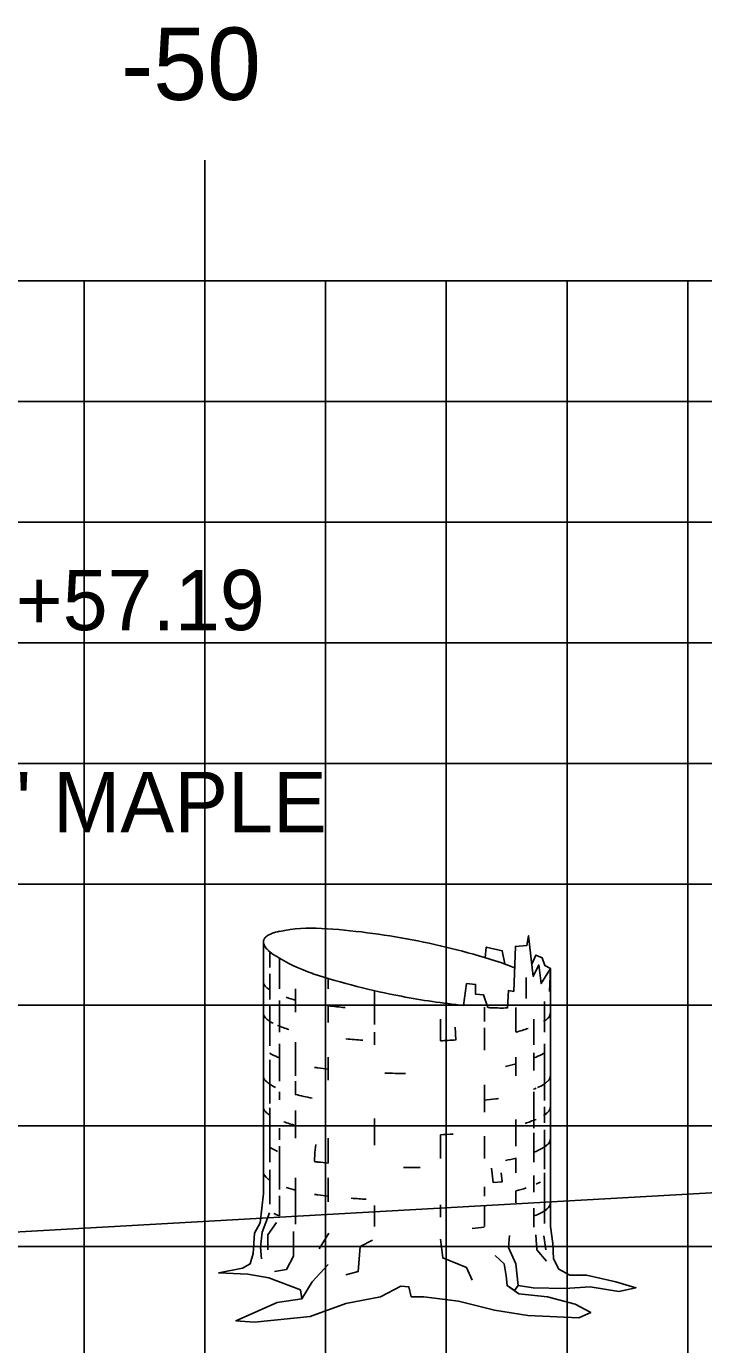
# Model space of a CAD drawing. Extents: x 854676 to 854846, y 366268 to 366378.
# Drawn here: x 854707.63 to 854713.24, y 366308.42 to 366319.35 of the extents above; entities that cross this region are included whole.
import ezdxf

# ---------------------------------------------------------------- set-up
doc = ezdxf.new("R2010")
doc.units = 0
for name, color, linetype in [('D_Text_Monospaced', 7, 'Continuous'), ('H_V ANNOTATION', 7, 'Continuous'), ('MAJOR', 7, 'Continuous'), ('MINOR', 7, 'Continuous'), ('S_Roadway_Centerline', 7, 'Continuous'), ('S_Trees_Decid_Pay', 7, 'Continuous')]:
    doc.layers.add(name, color=color, linetype=linetype)

msp = doc.modelspace()

# ---------------------------------------------------------------- linework, layer by layer
at = {"layer": 'MAJOR'}
for p, q in [((854709.106, 366318.238), (854709.106, 366317.236)), ((854689.106, 366317.236), (854829.106, 366317.236)), ((854689.106, 366317.236), (854829.106, 366317.236)), ((854709.106, 366302.236), (854709.106, 366317.236)), ((854689.106, 366312.236), (854829.106, 366312.236))]:
    msp.add_line(p, q, dxfattribs=at)
at = {"layer": 'MINOR'}
for p, q in [((854708.106, 366302.236), (854708.106, 366317.236)), ((854710.106, 366302.236), (854710.106, 366317.236)), ((854711.106, 366302.236), (854711.106, 366317.236)), ((854712.106, 366302.236), (854712.106, 366317.236)), ((854713.106, 366302.236), (854713.106, 366317.236)), ((854689.106, 366316.236), (854829.106, 366316.236)), ((854689.106, 366315.236), (854829.106, 366315.236)), ((854689.106, 366314.236), (854829.106, 366314.236)), ((854689.106, 366313.236), (854829.106, 366313.236)), ((854689.106, 366311.236), (854829.106, 366311.236)), ((854689.106, 366310.236), (854829.106, 366310.236)), ((854689.106, 366309.236), (854829.106, 366309.236))]:
    msp.add_line(p, q, dxfattribs=at)
at = {"layer": 'S_Roadway_Centerline'}
msp.add_lwpolyline([(854702.478, 366309.069), (854721.133, 366310.121), (854725.449, 366310.212), (854732.94, 366310.746), (854735.545, 366310.37), (854737.315, 366310.547), (854738.261, 366310.513), (854740.788, 366310.363), (854741.663, 366310.048), (854741.948, 366309.957), (854743.884, 366310.025), (854748.429, 366310.204), (854751.474, 366310.169), (854759.551, 366310.169), (854768.432, 366309.965), (854771.526, 366309.892)], dxfattribs=at)
at = {"layer": 'S_Trees_Decid_Pay'}
for p, q in [((854709.643, 366311.668), (854709.643, 366311.547)), ((854709.723, 366311.623), (854709.723, 366311.37)), ((854709.643, 366311.495), (854709.643, 366311.281)), ((854710.128, 366311.457), (854710.128, 366311.37)), ((854711.768, 366311.465), (854711.768, 366311.29)), ((854709.856, 366311.37), (854709.856, 366311.178)), ((854710.511, 366311.356), (854710.511, 366311.075)), ((854709.643, 366311.236), (854709.643, 366310.898)), ((854709.723, 366311.274), (854709.723, 366311.01)), ((854710.128, 366311.229), (854710.128, 366311.09)), ((854711.422, 366311.218), (854711.422, 366311.098)), ((854711.683, 366311.216), (854711.683, 366311.011)), ((854711.918, 366311.264), (854711.918, 366311.01)), ((854711.057, 366311.119), (854711.057, 366310.939)), ((854711.832, 366311.119), (854711.832, 366310.907)), ((854710.511, 366311.01), (854710.511, 366310.907)), ((854711.184, 366310.946), (854711.179, 366311.053)), ((854711.422, 366311.047), (854711.422, 366310.862)), ((854709.723, 366310.913), (854709.723, 366310.604)), ((854709.856, 366310.927), (854709.856, 366310.65)), ((854711.832, 366310.841), (854711.832, 366310.693)), ((854711.918, 366310.913), (854711.918, 366310.444)), ((854709.643, 366310.781), (854709.643, 366310.421)), ((854710.128, 366310.804), (854710.128, 366310.612)), ((854711.683, 366310.804), (854711.683, 366310.65)), ((854709.723, 366310.516), (854709.723, 366310.449)), ((854709.856, 366310.604), (854709.856, 366310.495)), ((854711.422, 366310.575), (854711.422, 366310.347)), ((854711.832, 366310.516), (854711.832, 366310.215)), ((854709.643, 366310.384), (854709.643, 366309.935)), ((854709.856, 366310.361), (854709.856, 366310.133)), ((854710.511, 366310.295), (854710.511, 366310.075)), ((854711.918, 366310.392), (854711.918, 366310.259)), ((854709.723, 366310.215), (854709.723, 366310.118)), ((854711.683, 366310.287), (854711.683, 366310.067)), ((854711.918, 366310.201), (854711.918, 366309.875)), ((854710.128, 366310.133), (854710.128, 366309.925)), ((854711.057, 366310.161), (854711.057, 366309.964)), ((854711.422, 366310.149), (854711.422, 366309.964)), ((854711.832, 366310.178), (854711.832, 366309.935)), ((854709.723, 366310.067), (854709.723, 366309.707)), ((854711.683, 366309.967), (854711.683, 366309.846)), ((854709.643, 366309.869), (854709.643, 366309.587)), ((854709.856, 366309.803), (854709.856, 366309.42)), ((854710.128, 366309.803), (854710.128, 366309.604)), ((854711.832, 366309.824), (854711.832, 366309.684)), ((854711.918, 366309.846), (854711.918, 366309.426)), ((854709.723, 366309.655), (854709.723, 366309.488)), ((854711.422, 366309.729), (854711.422, 366309.652)), ((854711.683, 366309.696), (854711.683, 366309.597)), ((854710.511, 366309.575), (854710.511, 366309.402)), ((854711.057, 366309.581), (854711.057, 366309.478)), ((854711.422, 366309.575), (854711.422, 366309.402)), ((854711.832, 366309.552), (854711.832, 366309.396)), ((854710.133, 366309.346), (854710.053, 366309.215)), ((854711.914, 366309.323), (854711.929, 366309.206))]:
    msp.add_line(p, q, dxfattribs=at)
for points in [[(854711.968, 366311.539), (854711.968, 366309.402), (854711.989, 366309.26), (854711.994, 366309.134), (854712.038, 366309.047), (854712.13, 366308.998), (854712.266, 366308.998), (854712.509, 366308.942), (854712.676, 366308.893), (854712.534, 366308.862), (854712.297, 366308.9), (854712.087, 366308.887), (854711.826, 366308.893), (854711.702, 366308.911), (854711.672, 366308.869), (854711.609, 366308.911), (854711.708, 366308.844), (854711.943, 366308.819), (854712.174, 366308.757), (854712.303, 366308.687), (854712.204, 366308.644), (854711.782, 366308.663), (854711.504, 366308.706), (854711.206, 366308.782), (854710.92, 366308.819), (854710.815, 366308.819), (854710.796, 366308.9), (854710.728, 366308.905), (854710.561, 366308.819), (854710.275, 366308.763), (854709.977, 366308.656), (854709.517, 366308.607), (854709.363, 366308.619), (854709.705, 366308.77), (854709.908, 366308.801), (854709.897, 366308.875), (854709.637, 366308.974), (854709.462, 366309.005), (854709.221, 366309.016), (854709.419, 366309.054), (854709.481, 366309.091), (854709.505, 366309.177), (854709.517, 366309.346), (854709.563, 366309.432), (854709.591, 366309.673), (854709.591, 366311.759)], [(854711.59, 366311.577), (854711.569, 366311.685), (854711.437, 366311.716), (854711.429, 366311.628)], [(854711.612, 366311.211), (854711.62, 366311.356), (854711.665, 366311.348), (854711.679, 366311.722), (854711.774, 366311.73), (854711.788, 366311.81), (854711.826, 366311.473), (854711.871, 366311.568), (854711.891, 366311.413), (854711.968, 366311.539), (854711.962, 366311.349)], [(854711.968, 366311.539), (854711.922, 366311.562), (854711.9, 366311.627), (854711.848, 366311.65), (854711.815, 366311.575)], [(854711.45, 366311.216), (854711.414, 366311.319), (854711.348, 366311.325), (854711.348, 366311.407), (854711.274, 366311.413), (854711.249, 366311.233)], [(854710.015, 366309.938), (854710.016, 366310.015), (854710.024, 366310.081)], [(854711.56, 366309.846), (854711.569, 366309.772), (854711.494, 366309.766), (854711.48, 366309.883)], [(854709.641, 366309.515), (854709.581, 366309.354), (854709.567, 366309.229), (854709.575, 366309.132)], [(854709.698, 366309.434), (854709.627, 366309.331), (854709.627, 366309.206)], [(854709.839, 366309.36), (854709.839, 366309.155), (854709.781, 366309.045), (854709.684, 366309.029)], [(854711.702, 366308.911), (854711.683, 366309.091), (854711.622, 366309.227), (854711.628, 366309.327)], [(854711.848, 366309.331), (854711.855, 366309.206), (854711.937, 366309.112)], [(854710.494, 366309.286), (854710.391, 366309.235), (854710.376, 366309.029), (854710.273, 366309)], [(854711.059, 366309.295), (854711.076, 366309.14), (854711.274, 366309.06), (854711.319, 366308.957)], [(854711.511, 366309.159), (854711.585, 366309.091), (854711.603, 366308.992), (854711.609, 366308.911)], [(854709.908, 366308.801), (854709.995, 366308.942), (854710.127, 366309.085)]]:
    msp.add_lwpolyline(points, dxfattribs=at)
for centre, radius, start, end in [((854709.715, 366311.673), 0.164, 110.0157, 124.2221), ((854709.823, 366311.377), 0.48, 101.7221, 110.0157), ((854709.989, 366310.574), 1.299, 86.3056, 101.7221), ((854709.678, 366305.758), 6.126, 79.2221, 86.3056), ((854709.637, 366311.759), 0.0467, 169.2221, 180.9043), ((854709.645, 366311.759), 0.0544, 180.9043, 191.7221), ((854709.637, 366311.759), 0.0467, 157.54, 169.2221), ((854709.655, 366311.762), 0.0645, 191.7221, 204.3989), ((854709.645, 366311.756), 0.0544, 146.7221, 157.54), ((854709.694, 366311.779), 0.107, 204.3989, 214.2221), ((854709.653, 366311.751), 0.0645, 134.0453, 146.7221), ((854709.741, 366311.811), 0.164, 214.2221, 228.4286), ((854709.683, 366311.72), 0.107, 124.2221, 134.0453), ((854709.678, 366305.758), 6.126, 72.1387, 79.2221), ((854709.95, 366312.047), 0.48, 228.4286, 236.7221), ((854710.4, 366312.733), 1.299, 236.7221, 252.1387), ((854711.88, 366317.326), 6.126, 252.1387, 259.2221), ((854711.158, 366310.351), 1.299, 66.6931, 72.1387), ((854709.645, 366311.433), 0.0554, 191.6815, 202.5), ((854709.654, 366311.437), 0.0657, 202.5, 215.1737), ((854709.69, 366311.462), 0.109, 215.1737, 225), ((854709.731, 366311.502), 0.166, 225, 238.33), ((854710.202, 366312.521), 1.292, 250.9084, 254.4349), ((854711.88, 366317.326), 6.126, 259.2221, 264.0853), ((854710.778, 366317.109), 5.916, 263.6913, 265.0485), ((854711.88, 366317.326), 6.126, 265.9754, 266.3056), ((854711.569, 366312.51), 1.299, 266.3056, 271.8711), ((854711.92, 366311.17), 0.0476, 348.3185, 0), ((854709.646, 366311.172), 0.0554, 191.6815, 202.5), ((854709.655, 366311.176), 0.0657, 202.5, 215.1737), ((854709.691, 366311.201), 0.109, 215.1737, 225), ((854709.732, 366311.241), 0.166, 225, 239.1924), ((854709.894, 366311.514), 0.484, 239.1924, 242.5838), ((854710.203, 366312.261), 1.292, 247.5, 251.9171), ((854711.827, 366311.241), 0.166, 300.8076, 315), ((854711.868, 366311.201), 0.109, 315, 324.8263), ((854711.903, 366311.176), 0.0657, 324.8263, 337.5), ((854711.913, 366311.172), 0.0554, 337.5, 348.3185), ((854710.779, 366316.849), 5.916, 265.1076, 266.4618), ((854711.355, 366312.261), 1.292, 284.7144, 289.3881), ((854710.779, 366316.849), 5.916, 272.6957, 273.9224), ((854711.827, 366310.978), 0.166, 300.8076, 302.9622), ((854709.732, 366310.978), 0.166, 238.3999, 239.1924), ((854709.894, 366311.251), 0.484, 239.1924, 247.5), ((854710.203, 366311.997), 1.292, 247.5, 248.1929), ((854711.355, 366311.997), 1.292, 280.7368, 284.7144), ((854711.355, 366311.997), 1.292, 291.6463, 292.5), ((854711.664, 366311.251), 0.484, 292.5, 300.8076), ((854709.646, 366310.651), 0.0554, 191.6815, 202.5), ((854709.655, 366310.655), 0.0657, 202.5, 215.1737), ((854710.203, 366311.997), 1.292, 261.6338, 262.8454), ((854710.779, 366316.585), 5.916, 262.8454, 263.6816), ((854710.779, 366316.585), 5.916, 268.2292, 269.8838), ((854711.903, 366310.655), 0.0657, 324.8263, 337.5), ((854711.913, 366310.651), 0.0554, 337.5, 348.3185), ((854711.92, 366310.649), 0.0476, 348.3185, 0), ((854709.691, 366310.68), 0.109, 215.1737, 225), ((854709.732, 366310.721), 0.166, 225, 239.1924), ((854709.894, 366310.993), 0.484, 239.1924, 245.3628), ((854711.355, 366311.74), 1.292, 291.5158, 292.5), ((854711.664, 366310.993), 0.484, 294.2275, 300.8076), ((854711.827, 366310.721), 0.166, 300.8076, 315), ((854711.868, 366310.68), 0.109, 315, 324.8263), ((854710.203, 366311.74), 1.292, 254.3895, 260.7435), ((854710.779, 366316.328), 5.916, 276.2405, 277.1546), ((854711.355, 366311.74), 1.292, 277.1546, 278.1274), ((854709.646, 366310.394), 0.0554, 191.6815, 202.5), ((854709.655, 366310.398), 0.0657, 202.5, 215.1737), ((854709.691, 366310.423), 0.109, 215.1737, 225), ((854709.732, 366310.463), 0.166, 225, 237.9306), ((854711.827, 366310.463), 0.166, 300.8076, 315), ((854711.868, 366310.423), 0.109, 315, 324.8263), ((854711.903, 366310.398), 0.0657, 324.8263, 337.5), ((854711.913, 366310.394), 0.0554, 337.5, 348.3185), ((854711.92, 366310.392), 0.0476, 348.3185, 0), ((854710.203, 366311.482), 1.292, 249.8999, 254.3895), ((854711.355, 366311.482), 1.292, 288.201, 292.5), ((854709.646, 366310.128), 0.0554, 191.6815, 202.5), ((854710.779, 366316.07), 5.916, 272.6957, 273.7279), ((854711.827, 366310.198), 0.166, 300.8076, 315), ((854711.868, 366310.157), 0.109, 315, 324.8263), ((854711.903, 366310.132), 0.0657, 324.8263, 337.5), ((854711.913, 366310.128), 0.0554, 337.5, 348.3185), ((854711.92, 366310.126), 0.0476, 348.3185, 0), ((854709.732, 366310.198), 0.166, 237.9306, 239.1924), ((854709.894, 366310.47), 0.484, 239.1924, 247.5), ((854711.355, 366311.217), 1.292, 280.7537, 284.7144), ((854711.355, 366311.217), 1.292, 291.6463, 292.5), ((854711.664, 366310.47), 0.484, 292.5, 300.8076), ((854710.203, 366311.217), 1.292, 261.6205, 262.8454), ((854710.779, 366315.805), 5.916, 262.8454, 263.6816), ((854710.779, 366315.805), 5.916, 269.7243, 270), ((854710.779, 366315.805), 5.916, 270, 271.0793), ((854709.646, 366309.856), 0.0554, 191.6815, 202.5), ((854709.655, 366309.86), 0.0657, 202.5, 215.1737), ((854709.691, 366309.885), 0.109, 215.1737, 225), ((854709.732, 366309.926), 0.166, 225, 237.9306), ((854711.664, 366310.199), 0.484, 292.5, 297.266), ((854710.203, 366310.945), 1.292, 250.8466, 254.3895), ((854710.203, 366310.945), 1.292, 261.6338, 262.8454), ((854710.779, 366315.533), 5.916, 262.8454, 263.6816), ((854711.355, 366310.945), 1.292, 284.7144, 288.6336), ((854710.779, 366315.533), 5.916, 265.539, 266.7363), ((854711.827, 366309.668), 0.166, 300.8076, 315), ((854711.868, 366309.628), 0.109, 315, 324.8263), ((854711.903, 366309.603), 0.0657, 324.8263, 337.5), ((854711.913, 366309.599), 0.0554, 337.5, 348.3185), ((854711.92, 366309.597), 0.0476, 348.3185, 0), ((854709.894, 366309.941), 0.484, 243.4501, 247.5), ((854710.194, 366310.691), 1.292, 247.9396, 248.6304), ((854711.355, 366310.688), 1.292, 291.6463, 292.5), ((854711.664, 366309.941), 0.484, 292.5, 300.8076), ((854710.779, 366315.276), 5.916, 275.2344, 276.2169)]:
    msp.add_arc(centre, radius, start, end, dxfattribs=at)

# ---------------------------------------------------------------- texts
at = {"layer": 'D_Text_Monospaced'}
for s, p in [('STA. 278+57.19', (854704.751, 366314.342)), ('EXIST. 6" MAPLE', (854704.751, 366312.668))]:
    msp.add_text(s, height=0.49998, dxfattribs=at).set_placement(p)
at = {"layer": 'H_V ANNOTATION'}
msp.add_text('-50', height=0.6, dxfattribs=at).set_placement((854708.411, 366318.736))

doc.saveas('drawing.dxf')
